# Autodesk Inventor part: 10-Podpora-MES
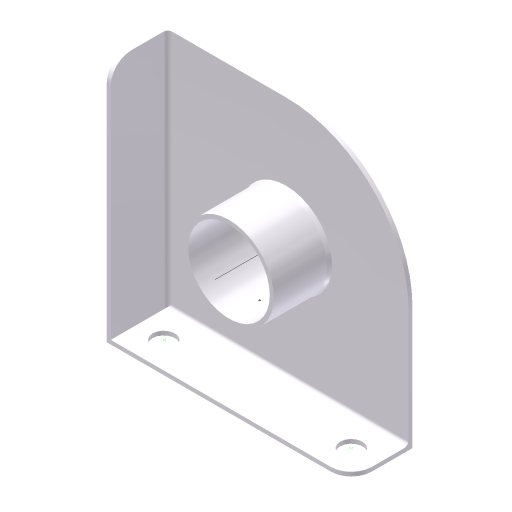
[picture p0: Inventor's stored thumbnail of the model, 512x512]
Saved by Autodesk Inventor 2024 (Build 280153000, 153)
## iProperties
Company: ATC
Shininess: 0.0
Length Units: 11269
Angle Units: 11279
Time Units: 11290
Mass Units: 11283
Length Display Precision: 3
Angle Display Precision: 2
Compacted: True
Created: 2023-03
Part Number: 10-Podpora-MES
Document SubType Name: Modeling
Designer: Andrzej Jaskulski
Material: Stal, Kurs-AJ
Density: 7.85 g/cm^3
Stock Number: Podpora-RP
Mass: 2849.83 g
Surface Area: 1845.04 cm^2
Volume: 362.113 cm^3
Appearance: Kurs-AJ
Checked By: A.J.
Engr Approved By: Andrzej Jaskulski
Mfg Approved By: Andrzej Jaskulski
Authority: A.J.
Density: 0.0
Volumn: 0.0
Area: 0.0
PropertySet Name: Model Information
Control State: 0
Master: False
Checked Out: False
Title: A.J.: Kurs R2024-MEP
Author: Andrzej Jaskulski
Revision Number: 1/24
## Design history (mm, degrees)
node "Baza" dims "d1" = 60, "d2" = 0
  sketch "Sketch1"
    geometry: L1 (0, 0)-(240, 0); L2 (240, 0)-(240, 240); L3 (240, 240)-(0, 240); L4 (0, 240)-(0, 0)
    constraints: 8 end point, 2 parallel, 2 perpendicular, 1 horizontal, 1 other
    dimensions: "d0" = 240 distance of L1.start L1.end
node "OTW" dims "d5" = 80, "d6" = 4, "d7" = 2, "d8" = 60 deg, "d9" = 8, "d10" = 118 deg, "d37" = 6
  sketch "Sketch3"
    geometry: L1 (0, 0)-(240, 0) reference; L2 (0, 240)-(0, 0) reference; 1 further point
    dimensions: "d3" = 120 distance from line of L1 point (120, 120); "d4" = 120 distance from line of L2 point (120, 120)
node "Oś konstrukcyjna1"
node "Płaszczyzna podziału"
feature "Podział1"
sketch "Szkic8"
  geometry: L1 (0, 0)-(0, 52) reference; L2 (216, 0)-(0, 0) reference; L3 (236, 52)-(236, 20) reference; C1 r 11 at (26, 26); C2 r 11 at (210, 26); C3 r 18.5 at (26, 26); C4 r 18.5 at (210, 26)
  constraints: 4 centre point, 2 coincident
  dimensions: "d63" = 22 diameter of C1; "d64" = 22 diameter of C2 (= d63); "d69" = 26 distance from line of C2.centre L3 (= d68); "d72" = 26 distance from line of L2 C2.centre; "d73" = 26 distance from line of C1.centre L2; "d74" = 26 distance from line of C1.centre L1; "d75" = 37 diameter of C3; "d76" = 37 diameter of C4
extrude "Otw. Fi22" cut sketch "Szkic8" extent not by distance; stored distance "d70" = 10; taper "d71" = 0 deg
feature "Podział2"
feature "Podział3"
feature "Podział4"
feature "Podział5"
node "Oś konstrukcyjna2"
node "Punkt przyłożenia"
node "Bryła1"
node "Korpusy bryłowe"
node "Korpusy powierzchniowe"
node "Zaokrąglenie1" dims "d12" = 20
node "Zaokrąglenie2" dims "d13" = 120
node "Skorupa" dims "d14" = 4
node "Zaokrąglenie3" dims "d30" = 4
node "Faza" dims "d31" = 4, "d32" = 1, "d35" = 45 deg
sketch "Szkic6"
  geometry: 1 further point
sketch "Szkic7"
  geometry: 1 further point
other parameters: "d55" = 0, "d68" = 26
